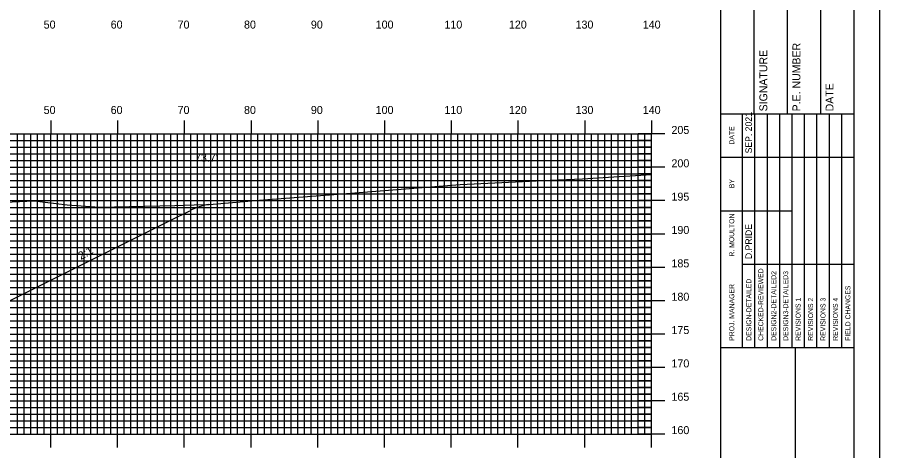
# Model space of a CAD drawing. Extents: x 1794453 to 1794796, y 442591 to 442811.
# Drawn here: x 1794663.3 to 1794792.6, y 442671.2 to 442736.2 of the extents above; entities that cross this region are included whole.
import ezdxf

# ---------------------------------------------------------------- set-up
doc = ezdxf.new("R2010")
doc.units = 0
for name, color, linetype in [('ANNOTATION', 7, 'Continuous'), ('BORDER', 7, 'Continuous'), ('D_Roadway_Centerline', 7, 'Continuous'), ('D_Roadway_SlopeLines', 7, 'Continuous'), ('D_Text_Standard', 7, 'Continuous'), ('H_V ANNOTATION', 7, 'Continuous'), ('MAJOR', 7, 'Continuous'), ('MINOR', 7, 'Continuous'), ('PLOT BOUNDARY', 7, 'Continuous'), ('S_Roadway_Centerline', 7, 'Continuous')]:
    doc.layers.add(name, color=color, linetype=linetype)

msp = doc.modelspace()

# ---------------------------------------------------------------- linework, layer by layer
at = {"layer": 'BORDER'}
for p, q in [((1794768.74, 442596.67), (1794768.74, 442806.67)), ((1794773.74, 442721.67), (1794773.74, 442738.97)), ((1794778.74, 442721.67), (1794778.74, 442738.97)), ((1794783.74, 442721.67), (1794783.74, 442738.97)), ((1794768.74, 442721.67), (1794788.74, 442721.67)), ((1794768.74, 442686.67), (1794788.74, 442686.67)), ((1794779.92, 442616.67), (1794779.92, 442686.67))]:
    msp.add_line(p, q, dxfattribs=at)
msp.add_lwpolyline([(1794468.74, 442596.67), (1794788.74, 442596.67), (1794788.74, 442806.67), (1794468.74, 442806.67)], close=True, dxfattribs=at)
for points in [[(1794771.97, 442715.17), (1794771.97, 442721.67)], [(1794773.83, 442686.68), (1794773.83, 442721.67)], [(1794775.7, 442721.67), (1794775.7, 442686.68)], [(1794777.56, 442686.68), (1794777.56, 442721.67)], [(1794779.42, 442686.68), (1794779.42, 442721.67)], [(1794781.29, 442686.68), (1794781.29, 442721.67)], [(1794783.15, 442686.68), (1794783.15, 442721.67)], [(1794785.01, 442686.68), (1794785.01, 442721.67)], [(1794786.88, 442686.68), (1794786.88, 442721.67)], [(1794771.97, 442686.68), (1794771.97, 442720.26)], [(1794768.74, 442715.17), (1794788.74, 442715.17)], [(1794768.74, 442707.17), (1794771.97, 442707.17)], [(1794771.97, 442707.17), (1794779.42, 442707.17)], [(1794771.97, 442699.17), (1794788.74, 442699.17)]]:
    msp.add_lwpolyline(points, dxfattribs=at)
at = {"layer": 'D_Roadway_Centerline'}
msp.add_arc((1794693.65, 442698.23), 10, 99.4162, 116.5651, dxfattribs=at)
at = {"layer": 'D_Roadway_SlopeLines'}
for p, q in [((1794686.33, 442705.74), (1794689.18, 442707.17)), ((1794661.97, 442693.57), (1794686.33, 442705.74))]:
    msp.add_line(p, q, dxfattribs=at)
at = {"layer": 'MAJOR'}
for p, q in [((1794668.34, 442720.67), (1794668.34, 442718.67)), ((1794678.34, 442720.67), (1794678.34, 442718.67)), ((1794688.34, 442720.67), (1794688.34, 442718.67)), ((1794698.34, 442720.67), (1794698.34, 442718.67)), ((1794708.34, 442720.67), (1794708.34, 442718.67)), ((1794718.34, 442720.67), (1794718.34, 442718.67)), ((1794728.34, 442720.67), (1794728.34, 442718.67)), ((1794738.34, 442720.67), (1794738.34, 442718.67)), ((1794748.34, 442720.67), (1794748.34, 442718.67)), ((1794758.34, 442720.67), (1794758.34, 442718.67)), ((1794478.34, 442718.67), (1794758.34, 442718.67)), ((1794478.34, 442718.67), (1794758.34, 442718.67)), ((1794668.34, 442673.67), (1794668.34, 442718.67)), ((1794678.34, 442673.67), (1794678.34, 442718.67)), ((1794688.34, 442673.67), (1794688.34, 442718.67)), ((1794698.34, 442673.67), (1794698.34, 442718.67)), ((1794708.34, 442673.67), (1794708.34, 442718.67)), ((1794718.34, 442673.67), (1794718.34, 442718.67)), ((1794728.34, 442673.67), (1794728.34, 442718.67)), ((1794738.34, 442673.67), (1794738.34, 442718.67)), ((1794748.34, 442673.67), (1794748.34, 442718.67)), ((1794760.34, 442718.67), (1794756.34, 442718.67)), ((1794758.34, 442673.67), (1794758.34, 442718.67)), ((1794758.34, 442673.67), (1794758.34, 442718.67)), ((1794478.34, 442713.67), (1794758.34, 442713.67)), ((1794760.34, 442713.67), (1794756.34, 442713.67)), ((1794478.34, 442708.67), (1794758.34, 442708.67)), ((1794760.34, 442708.67), (1794756.34, 442708.67)), ((1794478.34, 442703.67), (1794758.34, 442703.67)), ((1794760.34, 442703.67), (1794756.34, 442703.67)), ((1794478.34, 442698.67), (1794758.34, 442698.67)), ((1794760.34, 442698.67), (1794756.34, 442698.67)), ((1794478.34, 442693.67), (1794758.34, 442693.67)), ((1794760.34, 442693.67), (1794756.34, 442693.67)), ((1794478.34, 442688.67), (1794758.34, 442688.67)), ((1794760.34, 442688.67), (1794756.34, 442688.67)), ((1794478.34, 442683.67), (1794758.34, 442683.67)), ((1794760.34, 442683.67), (1794756.34, 442683.67)), ((1794478.34, 442678.67), (1794758.34, 442678.67)), ((1794760.34, 442678.67), (1794756.34, 442678.67)), ((1794478.34, 442673.67), (1794758.34, 442673.67)), ((1794478.34, 442673.67), (1794758.34, 442673.67)), ((1794668.34, 442671.66), (1794668.34, 442673.67)), ((1794678.34, 442671.66), (1794678.34, 442673.67)), ((1794688.34, 442671.66), (1794688.34, 442673.67)), ((1794698.34, 442671.66), (1794698.34, 442673.67)), ((1794708.34, 442671.66), (1794708.34, 442673.67)), ((1794718.34, 442671.66), (1794718.34, 442673.67)), ((1794728.34, 442671.66), (1794728.34, 442673.67)), ((1794738.34, 442671.66), (1794738.34, 442673.67)), ((1794748.34, 442671.66), (1794748.34, 442673.67)), ((1794760.34, 442673.67), (1794756.34, 442673.67)), ((1794758.34, 442671.66), (1794758.34, 442673.67))]:
    msp.add_line(p, q, dxfattribs=at)
at = {"layer": 'MINOR'}
for p, q in [((1794663.34, 442673.67), (1794663.34, 442718.67)), ((1794664.34, 442673.67), (1794664.34, 442718.67)), ((1794665.34, 442673.67), (1794665.34, 442718.67)), ((1794666.34, 442673.67), (1794666.34, 442718.67)), ((1794667.34, 442673.67), (1794667.34, 442718.67)), ((1794669.34, 442673.67), (1794669.34, 442718.67)), ((1794670.34, 442673.67), (1794670.34, 442718.67)), ((1794671.34, 442673.67), (1794671.34, 442718.67)), ((1794672.34, 442673.67), (1794672.34, 442718.67)), ((1794673.34, 442673.67), (1794673.34, 442718.67)), ((1794674.34, 442673.67), (1794674.34, 442718.67)), ((1794675.34, 442673.67), (1794675.34, 442718.67)), ((1794676.34, 442673.67), (1794676.34, 442718.67)), ((1794677.34, 442673.67), (1794677.34, 442718.67)), ((1794679.34, 442673.67), (1794679.34, 442718.67)), ((1794680.34, 442673.67), (1794680.34, 442718.67)), ((1794681.34, 442673.67), (1794681.34, 442718.67)), ((1794682.34, 442673.67), (1794682.34, 442718.67)), ((1794683.34, 442673.67), (1794683.34, 442718.67)), ((1794684.34, 442673.67), (1794684.34, 442718.67)), ((1794685.34, 442673.67), (1794685.34, 442718.67)), ((1794686.34, 442673.67), (1794686.34, 442718.67)), ((1794687.34, 442673.67), (1794687.34, 442718.67)), ((1794689.34, 442673.67), (1794689.34, 442718.67)), ((1794690.34, 442673.67), (1794690.34, 442718.67)), ((1794691.34, 442673.67), (1794691.34, 442718.67)), ((1794692.34, 442673.67), (1794692.34, 442718.67)), ((1794693.34, 442673.67), (1794693.34, 442718.67)), ((1794694.34, 442673.67), (1794694.34, 442718.67)), ((1794695.34, 442673.67), (1794695.34, 442718.67)), ((1794696.34, 442673.67), (1794696.34, 442718.67)), ((1794697.34, 442673.67), (1794697.34, 442718.67)), ((1794699.34, 442673.67), (1794699.34, 442718.67)), ((1794700.34, 442673.67), (1794700.34, 442718.67)), ((1794701.34, 442673.67), (1794701.34, 442718.67)), ((1794702.34, 442673.67), (1794702.34, 442718.67)), ((1794703.34, 442673.67), (1794703.34, 442718.67)), ((1794704.34, 442673.67), (1794704.34, 442718.67)), ((1794705.34, 442673.67), (1794705.34, 442718.67)), ((1794706.34, 442673.67), (1794706.34, 442718.67)), ((1794707.34, 442673.67), (1794707.34, 442718.67)), ((1794709.34, 442673.67), (1794709.34, 442718.67)), ((1794710.34, 442673.67), (1794710.34, 442718.67)), ((1794711.34, 442673.67), (1794711.34, 442718.67)), ((1794712.34, 442673.67), (1794712.34, 442718.67)), ((1794713.34, 442673.67), (1794713.34, 442718.67)), ((1794714.34, 442673.67), (1794714.34, 442718.67)), ((1794715.34, 442673.67), (1794715.34, 442718.67)), ((1794716.34, 442673.67), (1794716.34, 442718.67)), ((1794717.34, 442673.67), (1794717.34, 442718.67)), ((1794719.34, 442673.67), (1794719.34, 442718.67)), ((1794720.34, 442673.67), (1794720.34, 442718.67)), ((1794721.34, 442673.67), (1794721.34, 442718.67)), ((1794722.34, 442673.67), (1794722.34, 442718.67)), ((1794723.34, 442673.67), (1794723.34, 442718.67)), ((1794724.34, 442673.67), (1794724.34, 442718.67)), ((1794725.34, 442673.67), (1794725.34, 442718.67)), ((1794726.34, 442673.67), (1794726.34, 442718.67)), ((1794727.34, 442673.67), (1794727.34, 442718.67)), ((1794729.34, 442673.67), (1794729.34, 442718.67)), ((1794730.34, 442673.67), (1794730.34, 442718.67)), ((1794731.34, 442673.67), (1794731.34, 442718.67)), ((1794732.34, 442673.67), (1794732.34, 442718.67)), ((1794733.34, 442673.67), (1794733.34, 442718.67)), ((1794734.34, 442673.67), (1794734.34, 442718.67)), ((1794735.34, 442673.67), (1794735.34, 442718.67)), ((1794736.34, 442673.67), (1794736.34, 442718.67)), ((1794737.34, 442673.67), (1794737.34, 442718.67)), ((1794739.34, 442673.67), (1794739.34, 442718.67)), ((1794740.34, 442673.67), (1794740.34, 442718.67)), ((1794741.34, 442673.67), (1794741.34, 442718.67)), ((1794742.34, 442673.67), (1794742.34, 442718.67)), ((1794743.34, 442673.67), (1794743.34, 442718.67)), ((1794744.34, 442673.67), (1794744.34, 442718.67)), ((1794745.34, 442673.67), (1794745.34, 442718.67)), ((1794746.34, 442673.67), (1794746.34, 442718.67)), ((1794747.34, 442673.67), (1794747.34, 442718.67)), ((1794749.34, 442673.67), (1794749.34, 442718.67)), ((1794750.34, 442673.67), (1794750.34, 442718.67)), ((1794751.34, 442673.67), (1794751.34, 442718.67)), ((1794752.34, 442673.67), (1794752.34, 442718.67)), ((1794753.34, 442673.67), (1794753.34, 442718.67)), ((1794754.34, 442673.67), (1794754.34, 442718.67)), ((1794755.34, 442673.67), (1794755.34, 442718.67)), ((1794756.34, 442673.67), (1794756.34, 442718.67)), ((1794757.34, 442673.67), (1794757.34, 442718.67)), ((1794478.34, 442717.67), (1794758.34, 442717.67)), ((1794758.34, 442717.67), (1794756.34, 442717.67)), ((1794478.34, 442716.67), (1794758.34, 442716.67)), ((1794758.34, 442716.67), (1794756.34, 442716.67)), ((1794478.34, 442715.67), (1794758.34, 442715.67)), ((1794478.34, 442714.67), (1794758.34, 442714.67)), ((1794758.34, 442715.67), (1794756.34, 442715.67)), ((1794758.34, 442714.67), (1794756.34, 442714.67)), ((1794478.34, 442712.67), (1794758.34, 442712.67)), ((1794758.34, 442712.67), (1794756.34, 442712.67)), ((1794478.34, 442711.67), (1794758.34, 442711.67)), ((1794478.34, 442710.67), (1794758.34, 442710.67)), ((1794758.34, 442711.67), (1794756.34, 442711.67)), ((1794758.34, 442710.67), (1794756.34, 442710.67)), ((1794478.34, 442709.67), (1794758.34, 442709.67)), ((1794758.34, 442709.67), (1794756.34, 442709.67)), ((1794478.34, 442707.67), (1794758.34, 442707.67)), ((1794478.34, 442706.67), (1794758.34, 442706.67)), ((1794758.34, 442707.67), (1794756.34, 442707.67)), ((1794758.34, 442706.67), (1794756.34, 442706.67)), ((1794478.34, 442705.67), (1794758.34, 442705.67)), ((1794758.34, 442705.67), (1794756.34, 442705.67)), ((1794478.34, 442704.67), (1794758.34, 442704.67)), ((1794758.34, 442704.67), (1794756.34, 442704.67)), ((1794478.34, 442702.67), (1794758.34, 442702.67)), ((1794478.34, 442701.67), (1794758.34, 442701.67)), ((1794758.34, 442702.67), (1794756.34, 442702.67)), ((1794758.34, 442701.67), (1794756.34, 442701.67)), ((1794478.34, 442700.67), (1794758.34, 442700.67)), ((1794758.34, 442700.67), (1794756.34, 442700.67)), ((1794478.34, 442699.67), (1794758.34, 442699.67)), ((1794758.34, 442699.67), (1794756.34, 442699.67)), ((1794478.34, 442697.67), (1794758.34, 442697.67)), ((1794758.34, 442697.67), (1794756.34, 442697.67)), ((1794478.34, 442696.67), (1794758.34, 442696.67)), ((1794758.34, 442696.67), (1794756.34, 442696.67)), ((1794478.34, 442695.67), (1794758.34, 442695.67)), ((1794758.34, 442695.67), (1794756.34, 442695.67)), ((1794478.34, 442694.67), (1794758.34, 442694.67)), ((1794758.34, 442694.67), (1794756.34, 442694.67)), ((1794478.34, 442692.67), (1794758.34, 442692.67)), ((1794758.34, 442692.67), (1794756.34, 442692.67)), ((1794478.34, 442691.67), (1794758.34, 442691.67)), ((1794758.34, 442691.67), (1794756.34, 442691.67)), ((1794478.34, 442690.67), (1794758.34, 442690.67)), ((1794758.34, 442690.67), (1794756.34, 442690.67)), ((1794478.34, 442689.67), (1794758.34, 442689.67)), ((1794758.34, 442689.67), (1794756.34, 442689.67)), ((1794478.34, 442687.67), (1794758.34, 442687.67)), ((1794758.34, 442687.67), (1794756.34, 442687.67)), ((1794478.34, 442686.67), (1794758.34, 442686.67)), ((1794758.34, 442686.67), (1794756.34, 442686.67)), ((1794478.34, 442685.67), (1794758.34, 442685.67)), ((1794758.34, 442685.67), (1794756.34, 442685.67)), ((1794478.34, 442684.67), (1794758.34, 442684.67)), ((1794758.34, 442684.67), (1794756.34, 442684.67)), ((1794478.34, 442682.67), (1794758.34, 442682.67)), ((1794758.34, 442682.67), (1794756.34, 442682.67)), ((1794478.34, 442681.67), (1794758.34, 442681.67)), ((1794758.34, 442681.67), (1794756.34, 442681.67)), ((1794478.34, 442680.67), (1794758.34, 442680.67)), ((1794478.34, 442679.67), (1794758.34, 442679.67)), ((1794758.34, 442680.67), (1794756.34, 442680.67)), ((1794758.34, 442679.67), (1794756.34, 442679.67)), ((1794478.34, 442677.67), (1794758.34, 442677.67)), ((1794758.34, 442677.67), (1794756.34, 442677.67)), ((1794478.34, 442676.67), (1794758.34, 442676.67)), ((1794478.34, 442675.67), (1794758.34, 442675.67)), ((1794758.34, 442676.67), (1794756.34, 442676.67)), ((1794758.34, 442675.67), (1794756.34, 442675.67)), ((1794478.34, 442674.67), (1794758.34, 442674.67)), ((1794758.34, 442674.67), (1794756.34, 442674.67))]:
    msp.add_line(p, q, dxfattribs=at)
at = {"layer": 'PLOT BOUNDARY'}
msp.add_lwpolyline([(1794452.55, 442590.55), (1794792.55, 442590.55), (1794792.55, 442810.55), (1794452.55, 442810.55)], close=True, dxfattribs=at)
at = {"layer": 'S_Roadway_Centerline'}
msp.add_lwpolyline([(1794654.74, 442708.17), (1794665.86, 442708.65), (1794670.78, 442708.05), (1794675.63, 442707.71), (1794686.91, 442707.96), (1794689.81, 442708.04), (1794692.08, 442708.09), (1794700.21, 442708.8), (1794710.74, 442709.59), (1794718.94, 442710.24), (1794729.69, 442711.08), (1794743.18, 442711.74), (1794748.01, 442711.96), (1794751.91, 442712.2), (1794758.34, 442712.59)], dxfattribs=at)

# ---------------------------------------------------------------- texts
at = {"layer": 'ANNOTATION'}
msp.add_text('2:1', height=1.2, rotation=29.7449, dxfattribs=at).set_placement((1794672.86, 442699.76))
msp.add_text('2:1', height=1.2, rotation=29.7449, dxfattribs=at).set_placement((1794672.86, 442699.76))
at = {"layer": 'BORDER'}
for s, height, p in [('P.E. NUMBER', 1.1811, (1794780.66, 442722.06)), ('SIGNATURE', 1.181, (1794775.7, 442722.06)), ('DATE', 1.181, (1794785.62, 442722.06)), ('SEP. 2021', 0.969, (1794773.39, 442715.76)), ('DATE', 0.743, (1794770.75, 442717.08)), ('BY', 0.743, (1794770.75, 442710.54)), ('R. MOULTON', 0.745, (1794770.75, 442700.28)), ('D.PRIDE', 0.969, (1794773.39, 442699.92)), ('CHECKED-REVIEWED', 0.7455, (1794775.1, 442687.65)), ('DESIGN2-DETAILED2', 0.7455, (1794777.04, 442687.65)), ('DESIGN3-DETAILED3', 0.7455, (1794778.83, 442687.65)), ('DESIGN-DETAILED', 0.7455, (1794773.31, 442687.65)), ('PROJ. MANAGER', 0.7455, (1794770.75, 442687.65)), ('FIELD CHANGES', 0.7455, (1794788.15, 442687.65)), ('REVISIONS 1', 0.7455, (1794780.69, 442687.65)), ('REVISIONS 2', 0.7455, (1794782.56, 442687.65)), ('REVISIONS 3', 0.7455, (1794784.42, 442687.65)), ('REVISIONS 4', 0.7455, (1794786.28, 442687.65))]:
    msp.add_text(s, height=height, rotation=90, dxfattribs=at).set_placement(p)
at = {"layer": 'D_Text_Standard'}
msp.add_text("73.7'", height=1.2, dxfattribs=at).set_placement((1794689.94, 442714.51))
at = {"layer": 'H_V ANNOTATION'}
for s, p in [('50', (1794667.27, 442734.47)), ('60', (1794677.31, 442734.47)), ('70', (1794687.34, 442734.47)), ('80', (1794697.29, 442734.47)), ('90', (1794707.31, 442734.47)), ('100', (1794717.02, 442734.47)), ('110', (1794727.32, 442734.47)), ('120', (1794736.98, 442734.47)), ('130', (1794746.97, 442734.47)), ('140', (1794757.04, 442734.47)), ('50', (1794667.27, 442721.67)), ('60', (1794677.31, 442721.67)), ('70', (1794687.34, 442721.67)), ('80', (1794697.29, 442721.67)), ('90', (1794707.31, 442721.67)), ('100', (1794717.02, 442721.67)), ('110', (1794727.32, 442721.67)), ('120', (1794736.98, 442721.67)), ('130', (1794746.97, 442721.67)), ('140', (1794757.04, 442721.67)), ('205', (1794761.34, 442718.67)), ('200', (1794761.34, 442713.67)), ('195', (1794761.34, 442708.67)), ('190', (1794761.34, 442703.67)), ('185', (1794761.34, 442698.67)), ('180', (1794761.34, 442693.67)), ('175', (1794761.34, 442688.67)), ('170', (1794761.34, 442683.67)), ('165', (1794761.34, 442678.67)), ('160', (1794761.34, 442673.67))]:
    msp.add_text(s, height=1.2, dxfattribs=at).set_placement(p)

doc.saveas('drawing.dxf')
